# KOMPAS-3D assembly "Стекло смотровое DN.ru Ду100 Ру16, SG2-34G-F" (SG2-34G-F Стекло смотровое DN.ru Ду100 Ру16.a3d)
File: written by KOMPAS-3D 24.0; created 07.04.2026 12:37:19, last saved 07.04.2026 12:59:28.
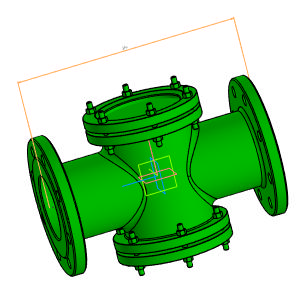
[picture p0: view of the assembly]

Document properties: Автор: Main; Полное имя файла: D:\DN.ru Аутсерс\Стекло смотровое DN.ru\Исходники\Стекло смотровое DN.ru SG2-34G-F тип В ГОСТ 21836-2021 Ду100 Ру16, углеродистая сталь, фланцевое\SG2-34G-F тип В Стекло смотровое DN.ru Ду100 Ру16.a3d

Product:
- Component [detail]: Деталь  | qty 1  | pos. 1  | Масса: 23.811038; Автор: Main; additional columns: Типовые; source file: ДетальДеталь.m3d
- Component [detail]: Стекло  | qty 2  | pos. 2  | Масса: 1.042745; Автор: Main; source file: СтеклоСтекло.m3d
- Component [detail]: ANSI B18.2.4.2M - M8x1,25 - 13  | designation ANSI B18.2.4.2M - M8x1,25  | qty 24  | pos. 3  | Масса: 0.006562; Комментарий: Типы метрических   шестигранных гаек   2; Автор: Main; additional columns: Сталь, мягкая; source file: ANSI B18.2.4.2M - M8x1,25ANSI B18.2.4.2M - M8x1,25 - 13.m3d
- Part/product: Стекло смотровое DN.ru Ду100 Ру16  | designation SG2-34G-F
    Масса: 26
    Раздел спецификации: Прочие изделия
    Примечание: D500-00087

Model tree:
1. Линейный размер:1  (labels: Грань.Твердое тело1; Ребро.Твердое тело1; Ребро.Solid1; Грань.Solid1)
     Значение = 350

Expressions: SG2-34G-F
Referenced files in D:\DN.ru Аутсерс\Стекло смотровое DN.ru\Исходники\Стекло смотровое DN.ru SG2-34G-F тип В ГОСТ 21836-2021 Ду100 Ру16, углеродистая сталь, фланцевое\: ДетальДеталь.m3d, СтеклоСтекло.m3d, ANSI B18.2.4.2M - M8x1,25ANSI B18.2.4.2M - M8x1,25 - 13.m3d
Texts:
  Точка начала. Х
  Точка начала. Y
  Точка начала. Z
  Стекло Стекло (1)
  Стекло Стекло (2)
  ANSI B18.2.4.2M - M8x1,25 ANSI B18.2.4.2M - M8x1,25 - 13 (1)
  ANSI B18.2.4.2M - M8x1,25 ANSI B18.2.4.2M - M8x1,25 - 13 (2)
  ANSI B18.2.4.2M - M8x1,25 ANSI B18.2.4.2M - M8x1,25 - 13 (3)
  ANSI B18.2.4.2M - M8x1,25 ANSI B18.2.4.2M - M8x1,25 - 13 (4)
  ANSI B18.2.4.2M - M8x1,25 ANSI B18.2.4.2M - M8x1,25 - 13 (5)
  ANSI B18.2.4.2M - M8x1,25 ANSI B18.2.4.2M - M8x1,25 - 13 (6)
  ANSI B18.2.4.2M - M8x1,25 ANSI B18.2.4.2M - M8x1,25 - 13 (7)
  ANSI B18.2.4.2M - M8x1,25 ANSI B18.2.4.2M - M8x1,25 - 13 (8)
  ANSI B18.2.4.2M - M8x1,25 ANSI B18.2.4.2M - M8x1,25 - 13 (9)
  ANSI B18.2.4.2M - M8x1,25 ANSI B18.2.4.2M - M8x1,25 - 13 (10)
  ANSI B18.2.4.2M - M8x1,25 ANSI B18.2.4.2M - M8x1,25 - 13 (11)
  ANSI B18.2.4.2M - M8x1,25 ANSI B18.2.4.2M - M8x1,25 - 13 (12)
  ANSI B18.2.4.2M - M8x1,25 ANSI B18.2.4.2M - M8x1,25 - 13 (13)
  ANSI B18.2.4.2M - M8x1,25 ANSI B18.2.4.2M - M8x1,25 - 13 (14)
  ANSI B18.2.4.2M - M8x1,25 ANSI B18.2.4.2M - M8x1,25 - 13 (15)
  ANSI B18.2.4.2M - M8x1,25 ANSI B18.2.4.2M - M8x1,25 - 13 (16)
  ANSI B18.2.4.2M - M8x1,25 ANSI B18.2.4.2M - M8x1,25 - 13 (17)
  ANSI B18.2.4.2M - M8x1,25 ANSI B18.2.4.2M - M8x1,25 - 13 (18)
  ANSI B18.2.4.2M - M8x1,25 ANSI B18.2.4.2M - M8x1,25 - 13 (19)
  ANSI B18.2.4.2M - M8x1,25 ANSI B18.2.4.2M - M8x1,25 - 13 (20)
  ANSI B18.2.4.2M - M8x1,25 ANSI B18.2.4.2M - M8x1,25 - 13 (21)
  ANSI B18.2.4.2M - M8x1,25 ANSI B18.2.4.2M - M8x1,25 - 13 (22)
  ANSI B18.2.4.2M - M8x1,25 ANSI B18.2.4.2M - M8x1,25 - 13 (23)
  ANSI B18.2.4.2M - M8x1,25 ANSI B18.2.4.2M - M8x1,25 - 13 (24)
  Ось Z.Начало координат
  Ось X.Начало координат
